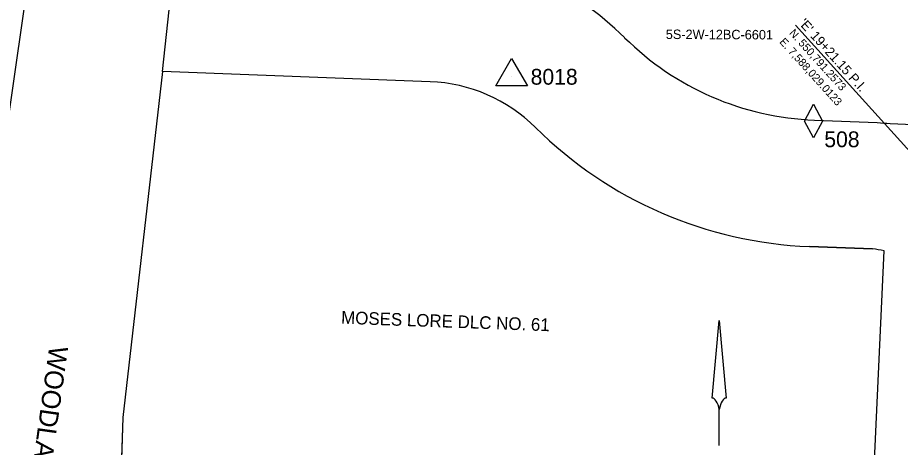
# Model space of a CAD drawing. Extents: x 7581380 to 7602708, y 543740 to 556109.
# Drawn here: x 7587436 to 7587995, y 550636 to 550907 of the extents above; entities that cross this region are included whole.
import ezdxf

# ---------------------------------------------------------------- set-up
doc = ezdxf.new("R2010")
doc.units = 0
for name, color, linetype in [('Default', 7, 'Continuous'), ('E_RDWY_ROAD_NameTx', 7, 'Continuous'), ('E_SURV_ALIGN_MinorTx', 7, 'Continuous'), ('E_SURV_BNDRY_CROW', 7, 'Continuous'), ('E_SURV_BNDRY_GovDLCLineTx', 7, 'Continuous'), ('E_SURV_BNDRY_OwnerTx', 7, 'Continuous'), ('E_SURV_BNDRY_Property', 7, 'Continuous'), ('E_SURV_NTW_SetNtwPt', 7, 'Continuous'), ('E_SURV_NTW_SetNtwPtTx', 7, 'Continuous'), ('E_SURV_NTW_SetStrategicPt', 7, 'Continuous'), ('E_SURV_NTW_SetStrategicPtTx', 7, 'Continuous'), ('P_ODOT_PLAN_General', 7, 'Continuous'), ('P_RW_FILE_AreaShapeRemain', 7, 'Continuous')]:
    doc.layers.add(name, color=color, linetype=linetype)

msp = doc.modelspace()

# ---------------------------------------------------------------- linework, layer by layer
at = {"layer": 'E_SURV_ALIGN_MinorTx'}
msp.add_lwpolyline([(7588029.01, 550791.26), (7587928.4, 550902.51)], dxfattribs=at)
at = {"layer": 'E_SURV_BNDRY_CROW'}
for p, q in [((7587454.09, 551007.61), (7587384.32, 550524.19)), ((7587528.03, 550873.08), (7587503.03, 550654.44)), ((7587697.35, 550866.68), (7587528.11, 550873.08)), ((7587988.26, 550840.31), (7588028.1, 550838.46)), ((7587965.01, 550339.35), (7587984.42, 550759.75)), ((7587503.03, 550654.44), (7587494.75, 550394.45))]:
    msp.add_line(p, q, dxfattribs=at)
for points in [[(7587940.33, 550842.42), (7587980.08, 550840.92)], [(7587977.06, 550760.97), (7587937.31, 550762.48)]]:
    msp.add_lwpolyline(points, dxfattribs=at)
for centre, radius, start, end in [((7587693.57, 550766.75), 180, 45.2227, 87.8328), ((7587947.13, 551022.29), 180, 225.2227, 267.8328), ((7587693.57, 550766.75), 100, 45.2227, 87.8328), ((7587947.13, 551022.29), 260, 225.2227, 267.8328), ((7587992.49, 550952.23), 112, 263.6363, 267.8321), ((7587962.49, 550649.92), 112, 78.7057, 82.526)]:
    msp.add_arc(centre, radius, start, end, dxfattribs=at)
at = {"layer": 'E_SURV_BNDRY_OwnerTx'}
for p, q in [((7587937.31, 550762.48), (7587977.06, 550760.97)), ((7587977.06, 550760.97), (7587937.31, 550762.48))]:
    msp.add_line(p, q, dxfattribs=at)
at = {"layer": 'E_SURV_BNDRY_Property'}
msp.add_line((7587528.11, 550873.08), (7587536.53, 550952.81), dxfattribs=at)
at = {"layer": 'E_SURV_NTW_SetNtwPt'}
for p, q in [((7587738.89, 550864.02), (7587748.89, 550881.34)), ((7587748.89, 550881.34), (7587758.89, 550864.02)), ((7587748.89, 550869.8), (7587748.89, 550869.8)), ((7587758.89, 550864.02), (7587738.89, 550864.02))]:
    msp.add_line(p, q, dxfattribs=at)
at = {"layer": 'E_SURV_NTW_SetStrategicPt'}
for p, q in [((7587934.16, 550841.79), (7587939.83, 550852.4)), ((7587939.83, 550852.4), (7587945.5, 550841.79)), ((7587939.83, 550852.4), (7587939.83, 550852.4)), ((7587939.83, 550831.19), (7587934.16, 550841.79)), ((7587939.83, 550841.79), (7587939.83, 550841.79)), ((7587945.5, 550841.79), (7587939.83, 550831.19))]:
    msp.add_line(p, q, dxfattribs=at)
at = {"layer": 'P_ODOT_PLAN_General'}
for p, q in [((7587875.69, 550666.63), (7587880.16, 550715.73)), ((7587880.16, 550715.73), (7587884.62, 550666.63)), ((7587880.16, 550636.63), (7587880.16, 550659.48))]:
    msp.add_line(p, q, dxfattribs=at)
for centre, major_axis, start_param, end_param in [((7587877.1, 550658.93), (1.4, -7.7), 1.570797, 3.143961), ((7587883.21, 550658.93), (1.4, 7.7), 6.280763, 7.853981)]:
    msp.add_ellipse(centre, major_axis=major_axis, ratio=0.396662, start_param=start_param, end_param=end_param, dxfattribs=at)
at = {"layer": 'P_RW_FILE_AreaShapeRemain'}
for p, q in [((7587937.31, 550762.48), (7587937.3, 550762.48)), ((7587977.06, 550760.97), (7587937.31, 550762.48)), ((7587977.06, 550760.97), (7587937.31, 550762.48)), ((7587967.13, 550385.17), (7587984.42, 550759.75)), ((7587967.13, 550385.17), (7587984.42, 550759.75))]:
    msp.add_line(p, q, dxfattribs=at)
msp.add_lwpolyline([(7587697.35, 550866.68), (7587528.11, 550873.08), (7587503.03, 550654.44), (7587498.41, 550509.6)], dxfattribs=at)
msp.add_lwpolyline([(7587697.35, 550866.68), (7587528.11, 550873.08), (7587503.03, 550654.44), (7587498.41, 550509.6)], dxfattribs=at)
for centre, radius, start, end in [((7587693.57, 550766.75), 100, 45.2227, 87.8328), ((7587693.57, 550766.75), 100, 45.2227, 87.8328), ((7587947.13, 551022.29), 260, 225.2227, 267.8328), ((7587947.13, 551022.29), 260, 225.2227, 267.8328), ((7587962.49, 550649.92), 112, 78.7057, 82.526), ((7587962.49, 550649.92), 112, 78.7057, 82.526)]:
    msp.add_arc(centre, radius, start, end, dxfattribs=at)

# ---------------------------------------------------------------- texts
at = {"layer": 'Default'}
msp.add_text('5S-2W-12BC-6601', height=6, rotation=359.7425, dxfattribs=at).set_placement((7587846.36, 550893.67))
at = {"layer": 'E_RDWY_ROAD_NameTx'}
msp.add_text('WOODLAND AVE', height=12, rotation=262.0229, dxfattribs=at).set_placement((7587456.55, 550700.16))
at = {"layer": 'E_SURV_ALIGN_MinorTx'}
for s, height, p in [("'E' 19+21.15 P.I.", 6, (7587930.29, 550903.23)), ('N. 550,791.2573', 5, (7587924.1, 550897.17)), ('E. 7,588,029.0123', 5, (7587917.92, 550891.58))]:
    msp.add_text(s, height=height, rotation=312.1235, dxfattribs=at).set_placement(p)
at = {"layer": 'E_SURV_BNDRY_GovDLCLineTx'}
msp.add_text('MOSES LORE DLC NO. 61', height=8, rotation=357.9244, dxfattribs=at).set_placement((7587640.93, 550713.69))
at = {"layer": 'E_SURV_NTW_SetNtwPtTx'}
msp.add_text('8018', height=10, dxfattribs=at).set_placement((7587760.89, 550864.8))
at = {"layer": 'E_SURV_NTW_SetStrategicPtTx'}
msp.add_text('508', height=10, dxfattribs=at).set_placement((7587946.6, 550825.27))

doc.saveas('drawing.dxf')
